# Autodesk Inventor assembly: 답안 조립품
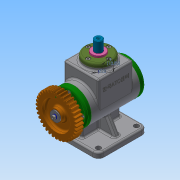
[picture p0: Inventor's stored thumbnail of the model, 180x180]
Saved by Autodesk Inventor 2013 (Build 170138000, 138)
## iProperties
Created: 2019-01
Part Number: 답안 조립품
Document SubType Name: Assembly
Designer: Administrator
Author: Administrator
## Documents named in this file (18)
- C:\Users\Administrator\Desktop\390107V1043\답안 조립품.iam
- C:\Users\Administrator\Desktop\390107V1043\본체.ipt
- C:\Users\Administrator\Desktop\390107V1043\베어링 6203.ipt
- C:\Users\Administrator\Desktop\390107V1043\편심축.ipt
- C:\Users\Administrator\Desktop\390107V1043\앞커버.ipt
- C:\Users\Administrator\Desktop\390107V1043\뒤커버.ipt
- C:\Users\Administrator\Desktop\390107V1043\상부커버.ipt
- C:\Users\Administrator\Desktop\390107V1043\볼트 M4.ipt
- C:\Users\Administrator\Desktop\390107V1043\오일 실 17 30 5.ipt
- C:\Users\Administrator\Desktop\390107V1043\키 4x4x12.ipt
- C:\Users\Administrator\Desktop\390107V1043\스퍼기어.ipt
- C:\Users\Administrator\Desktop\390107V1043\평와셔.ipt
- C:\Users\Administrator\Desktop\390107V1043\스프링와셔.ipt
- C:\Users\Administrator\Desktop\390107V1043\부시.ipt
- C:\Users\Administrator\Desktop\390107V1043\멈춤링.ipt
- C:\Users\Administrator\Desktop\390107V1043\슬라이더.ipt
- C:\Users\Administrator\Desktop\390107V1043\스프링조립용 와셔.ipt
- C:\Users\Administrator\Desktop\390107V1043\가변스프링.ipt
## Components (1 placed, 1 different names)
1. 가변스프링:1
